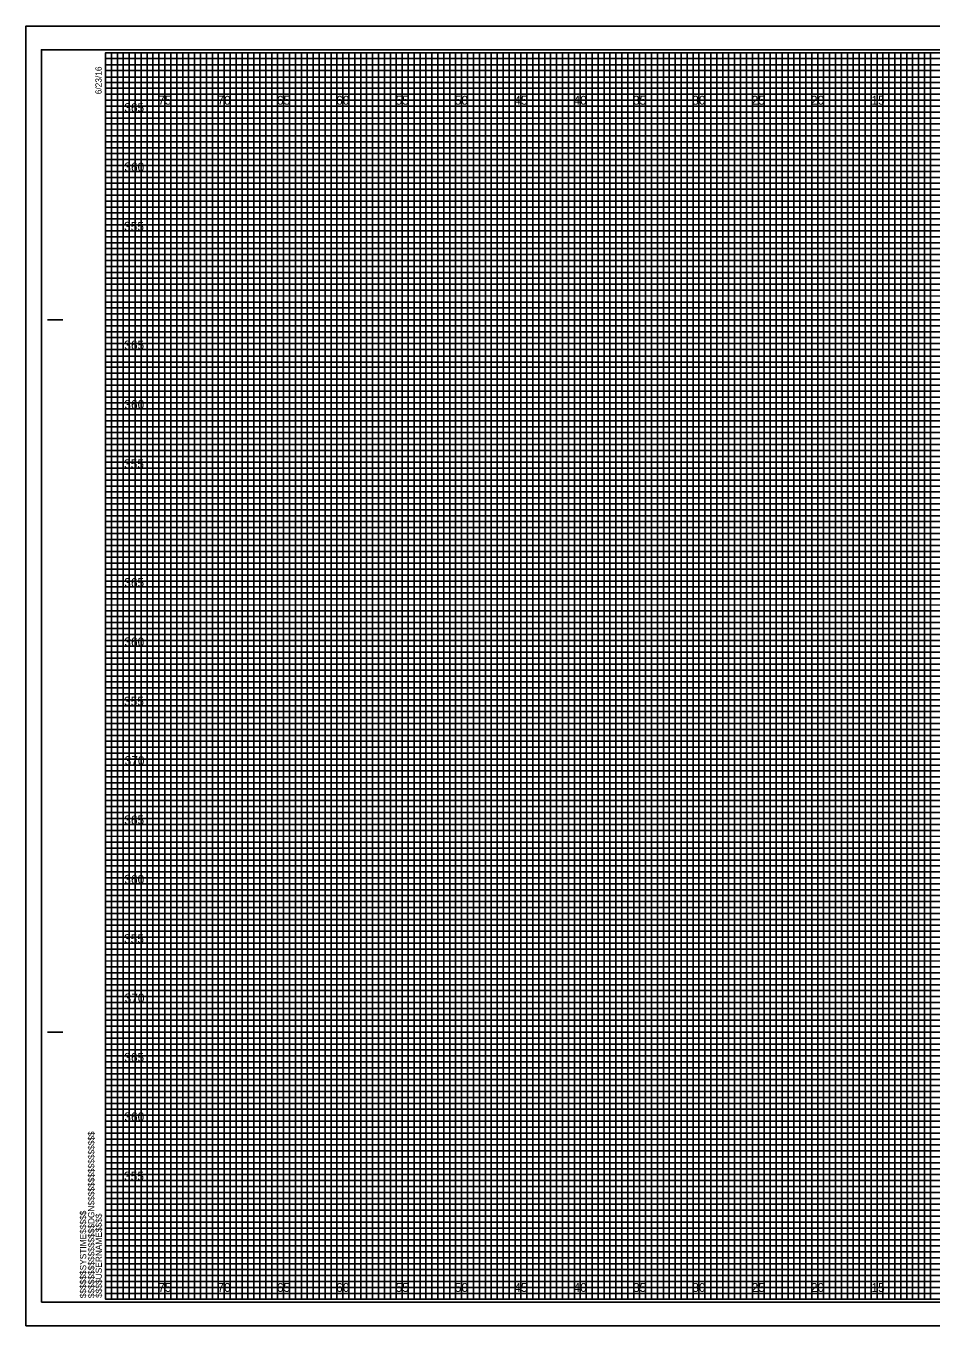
# Model space of a CAD drawing. Extents: x -7 to 162, y 658 to 767.
# Drawn here: x -6.7 to 69.5, y 657.8 to 767.2 of the extents above; entities that cross this region are included whole.
import ezdxf

# ---------------------------------------------------------------- set-up
doc = ezdxf.new("R2010")
doc.units = 0
for name, color, linetype in [('Prop XS Elevation Labels', 7, 'Continuous'), ('Prop XS Offset Labels', 7, 'Continuous'), ('Sheet Cross Section CELL', 7, 'Continuous'), ('Sheet Cross Section Grid Major CELL', 7, 'Continuous'), ('Sheet Cross Section Grid Middle CELL', 7, 'Continuous'), ('Sheet Cross Section Grid Minor 1 CELL', 7, 'Continuous'), ('Sheet Cross Section Grid Minor 2 CELL', 7, 'Continuous'), ('Sheet Cutting Line CELL', 7, 'Continuous'), ('Sheet DOT Grid CELL', 7, 'Continuous'), ('Sheet Plot Border Inside CELL', 7, 'Continuous'), ('Sheet Plot Border Outside CELL', 7, 'Continuous')]:
    doc.layers.add(name, color=color, linetype=linetype)

msp = doc.modelspace()

# ---------------------------------------------------------------- linework, layer by layer
at = {"layer": 'Sheet Cross Section CELL'}
for p, q in [((-4.9, 742.5), (-3.65, 742.5)), ((-4.85, 742.5), (-3.6, 742.5)), ((-4.9, 682.5), (-3.65, 682.5)), ((-4.85, 682.5), (-3.6, 682.5)), ((0, 660), (0, 660)), ((0, 660), (0, 660)), ((0, 660), (0, 660)), ((0, 660), (0, 660)), ((0, 660), (0, 660)), ((0, 660), (0, 660)), ((0, 660), (0, 660))]:
    msp.add_line(p, q, dxfattribs=at)
msp.add_lwpolyline([(160, 765), (0, 765), (0, 660), (160, 660)], close=True, dxfattribs=at)
at = {"layer": 'Sheet Cross Section Grid Major CELL'}
for p, q in [((5, 765), (0, 765)), ((5, 660), (5, 765)), ((15, 765), (10, 765)), ((10, 765), (10, 660)), ((15, 660), (15, 765)), ((25, 765), (20, 765)), ((20, 765), (20, 660)), ((25, 660), (25, 765)), ((35, 765), (30, 765)), ((30, 765), (30, 660)), ((35, 660), (35, 765)), ((45, 765), (40, 765)), ((40, 765), (40, 660)), ((45, 660), (45, 765)), ((55, 765), (50, 765)), ((50, 765), (50, 660)), ((55, 660), (55, 765)), ((65, 765), (60, 765)), ((60, 765), (60, 660)), ((65, 660), (65, 765)), ((10, 660), (5, 660)), ((20, 660), (15, 660)), ((30, 660), (25, 660)), ((40, 660), (35, 660)), ((50, 660), (45, 660)), ((60, 660), (55, 660)), ((70, 660), (65, 660))]:
    msp.add_line(p, q, dxfattribs=at)
for points in [[(0, 760), (160, 760), (160, 755), (0, 755)], [(0, 750), (160, 750), (160, 745), (0, 745)], [(0, 740), (160, 740), (160, 735), (0, 735)], [(0, 730), (160, 730), (160, 725), (0, 725)], [(0, 720), (160, 720), (160, 715), (0, 715)], [(0, 710), (160, 710), (160, 705), (0, 705)], [(0, 700), (160, 700), (160, 695), (0, 695)], [(0, 690), (160, 690), (160, 685), (0, 685)], [(0, 680), (160, 680), (160, 675), (0, 675)], [(0, 670), (160, 670), (160, 665), (0, 665)]]:
    msp.add_lwpolyline(points, dxfattribs=at)
at = {"layer": 'Sheet Cross Section Grid Middle CELL'}
for points in [[(0, 765), (2.5, 765), (2.5, 660), (7.5, 660), (7.5, 765), (12.5, 765), (12.5, 660), (17.5, 660), (17.5, 765), (22.5, 765), (22.5, 660), (27.5, 660), (27.5, 765), (32.5, 765), (32.5, 660), (37.5, 660), (37.5, 765), (42.5, 765), (42.5, 660), (47.5, 660), (47.5, 765), (52.5, 765), (52.5, 660), (57.5, 660), (57.5, 765), (62.5, 765), (62.5, 660), (67.5, 660), (67.5, 765), (72.5, 765)], [(0, 762.5), (137.5, 762.5)], [(0, 752.5), (160, 752.5), (160, 757.5), (0, 757.5)], [(0, 742.5), (160, 742.5), (160, 747.5), (0, 747.5)], [(0, 732.5), (160, 732.5), (160, 737.5), (0, 737.5)], [(0, 722.5), (160, 722.5), (160, 727.5), (0, 727.5)], [(0, 712.5), (160, 712.5), (160, 717.5), (0, 717.5)], [(0, 702.5), (160, 702.5), (160, 707.5), (0, 707.5)], [(0, 692.5), (160, 692.5), (160, 697.5), (0, 697.5)], [(0, 682.5), (160, 682.5), (160, 687.5), (0, 687.5)], [(0, 672.5), (160, 672.5), (160, 677.5), (0, 677.5)], [(0, 662.5), (160, 662.5), (160, 667.5), (0, 667.5)]]:
    msp.add_lwpolyline(points, dxfattribs=at)
at = {"layer": 'Sheet Cross Section Grid Minor 1 CELL'}
for p, q in [((0, 764.5), (130, 764.5)), ((130, 763.99), (0, 763.99)), ((0, 763.99), (0, 763.5)), ((0, 763.5), (130, 763.5)), ((130, 762.95), (0, 762.95)), ((0, 762.95), (0, 762)), ((0, 762), (160, 762))]:
    msp.add_line(p, q, dxfattribs=at)
for points in [[(0, 761.5), (135, 761.5), (160, 761.5), (160, 761), (0, 761)], [(0, 760.5), (160, 760.5), (160, 759.5), (0, 759.5)], [(0, 759), (160, 759), (160, 758.5), (0, 758.49)], [(0, 758), (160, 758), (160, 757), (0, 757)], [(0, 756.5), (160, 756.5), (160, 756), (0, 756)], [(0, 755.5), (160, 755.5), (160, 754.5), (0, 754.5)], [(0, 754), (160, 754), (160, 753.5), (0, 753.5)], [(0, 753), (160, 753), (160, 752), (0, 752)], [(0, 751.5), (160, 751.5), (160, 751), (0, 751)], [(0, 750.5), (160, 750.5), (160, 749.5), (0, 749.5)], [(0, 749), (160, 749), (160, 748.5), (0, 748.5)], [(0, 748), (160, 748), (160, 746.98), (160, 746.5), (160, 746), (0, 746)], [(0, 747), (160, 747), (160, 746.5), (0, 746.5)], [(0, 745.5), (160, 745.5), (160, 744.5), (0, 744.51)], [(0, 744.51), (160, 744.5), (160, 744), (0, 744)], [(0, 743.5), (160, 743.5), (160, 743), (0, 743)], [(0, 742), (160, 742), (160, 741.5), (0, 741.5)], [(0, 741), (160, 741), (160, 740.5), (0, 740.5)], [(-0.04, 739.45), (160, 739.45), (160, 738.94), (-0.04, 738.94)], [(0, 738.5), (160, 738.5), (160, 738), (0, 738)], [(0, 737), (160, 737), (160, 736.5), (0, 736.5)], [(0, 736), (160, 736), (160, 735.5), (0, 735.5)], [(0, 734.5), (160, 734.5), (160, 734), (0, 734)], [(0, 733.5), (160, 733.5), (160, 733), (0, 733)], [(0, 732), (160, 732), (160, 731.5), (0, 731.5)], [(0, 731), (160, 731), (160, 730.5), (0, 730.5)], [(0, 729.5), (160, 729.5), (160, 728.99), (0, 729)], [(0, 728.5), (160, 728.5), (160, 728), (0, 728)], [(0, 727), (160, 727), (160, 726.5), (0, 726.5)], [(0, 726), (160, 726), (160, 725.5), (0, 725.5)], [(0, 724.5), (160, 724.5), (160, 724), (0, 724)], [(0, 723.5), (160, 723.5), (160, 723), (0, 723)], [(0, 722), (160, 722), (160, 721.5), (0, 721.5)], [(0, 721), (160, 721), (160, 720.5), (0, 720.5)], [(0, 719.5), (160, 719.5), (160, 719), (0, 719)], [(0, 718.5), (160.03, 718.46), (160, 718), (0, 718)], [(0, 717), (160, 717), (160, 716.5), (0, 716.5)], [(0, 716), (160, 716), (160, 715.5), (0, 715.5)], [(0, 714.5), (160, 714.5), (160, 714), (0, 714)], [(0, 713.5), (160, 713.5), (160, 713), (0, 713)], [(0, 712), (160, 712), (160, 711.5), (0, 711.5)], [(0, 711), (160, 711), (160, 710.5), (0, 710.5)], [(0, 709.5), (160, 709.5), (160, 709), (0, 709)], [(0, 708.5), (160, 708.5), (160, 708), (0, 708)], [(0, 707), (160, 707), (160, 706.5), (0, 706.5)], [(0, 706), (160, 706), (160, 705.5), (0, 705.5)], [(0, 704.5), (160, 704.5), (160, 704), (0, 704)], [(0, 703.5), (160, 703.5), (160, 703), (0, 703)], [(0, 702), (160, 702), (160, 701.5), (0, 701.5)], [(0, 701), (160, 701), (160, 700.5), (0, 700.5)], [(0, 699.5), (160, 699.5), (160, 698.99), (0, 699)], [(0, 698.5), (160, 698.5), (160, 698), (0, 698)], [(0, 697), (160, 697), (160, 696.5), (0, 696.5)], [(0, 696), (160, 696), (160, 695.5), (0, 695.5)], [(0, 694.5), (160, 694.5), (160, 694), (0, 694)], [(0, 693.5), (160, 693.5), (160, 693), (0, 693)], [(0, 692), (160, 692), (160, 691.5), (0, 691.5)], [(0, 691), (160, 691), (160, 690.5), (0, 690.5)], [(0, 689.5), (160, 689.5), (160, 689), (0, 689)], [(0, 688.5), (160.03, 688.46), (160, 688), (0, 688)], [(0, 687), (160, 687), (160, 686.5), (0, 686.5)], [(0, 686), (160, 686), (160, 685.5), (0, 685.5)], [(0, 684.5), (160, 684.5), (160, 684), (0, 684)], [(0, 683.5), (160, 683.5), (160, 683), (0, 683)], [(0, 682), (160, 682), (160, 681.5), (0, 681.5)], [(0, 681), (160, 681), (160, 680.5), (0, 680.5)], [(0, 679.5), (160, 679.5), (160, 679), (0, 679)], [(0, 678.5), (160, 678.5), (160, 678), (0, 678)], [(0, 677), (160, 677), (160, 676.5), (0, 676.5)], [(0, 676), (160, 676), (160, 675.5), (0, 675.5)], [(0, 674.5), (160, 674.5), (160, 674), (0, 674)], [(0, 673.5), (160, 673.5), (160, 673), (0, 673)], [(0, 672), (160, 672), (160, 671.5), (0, 671.5)], [(0, 671), (160, 671), (160, 670.5), (0, 670.5)], [(0, 669.5), (160, 669.5), (160, 669), (0, 669)], [(0, 668.5), (160, 668.5), (160, 668), (0, 668)], [(0, 667), (160, 667), (160, 666.5), (0, 666.5)], [(0, 666), (160, 666), (160, 665.5), (0, 665.5)], [(0, 664.5), (160, 664.5), (160, 664), (0, 664)], [(0, 663.5), (160, 663.5), (160, 663), (0, 663)], [(0, 662), (160, 662), (160, 661.5), (0, 661.5)], [(0, 661), (160, 661), (160, 660.5), (0, 660.5)]]:
    msp.add_lwpolyline(points, dxfattribs=at)
at = {"layer": 'Sheet Cross Section Grid Minor 2 CELL'}
for points in [[(0, 660), (0.5, 660), (0.5, 765), (1, 765), (1, 660)], [(1, 660), (1.5, 660), (1.5, 765), (2, 765), (2, 660)], [(2.5, 660), (3, 660), (3, 765), (3.5, 765), (3.5, 660)], [(3.5, 660), (4, 660), (4, 765), (4.5, 765), (4.5, 660)], [(5, 660), (5.5, 660), (5.5, 765), (6, 765), (6, 660)], [(6, 660), (6.5, 660), (6.5, 765), (7, 765), (7, 660)], [(7.5, 660), (8, 660), (8, 765), (8.5, 765), (8.5, 660)], [(8.5, 660), (9, 660), (9, 765), (9.5, 765), (9.5, 660)], [(10, 660), (10.5, 660), (10.5, 765), (11, 765), (11, 660)], [(11, 660), (11.5, 660), (11.5, 765), (12, 765), (12, 660)], [(12.5, 660), (13, 660), (13, 765), (13.5, 765), (13.5, 660)], [(13.5, 660), (14, 660), (14, 765), (14.5, 765), (14.5, 660)], [(15, 660), (15.5, 660), (15.5, 765), (16, 765), (16, 660)], [(16, 660), (16.5, 660), (16.5, 765), (17, 765), (17, 660)], [(17.5, 660), (18, 660), (18, 765), (18.5, 765), (18.5, 660)], [(18.5, 660), (19, 660), (19, 765), (19.5, 765), (19.5, 660)], [(20, 660), (20.5, 660), (20.5, 765), (21, 765), (21, 660)], [(21, 660), (21.5, 660), (21.5, 765), (22, 765), (22, 660)], [(22.5, 660), (23, 660), (23, 765), (23.5, 765), (23.5, 660)], [(23.5, 660), (24, 660), (24, 765), (24.5, 765), (24.5, 660)], [(25, 660), (25.5, 660), (25.5, 765), (26, 765), (26, 660)], [(26, 660), (26.5, 660), (26.5, 765), (27, 765), (27, 660)], [(27.5, 660), (28, 660), (28, 765), (28.5, 765), (28.5, 660)], [(28.5, 660), (29, 660), (29, 765), (29.5, 765), (29.5, 660)], [(30, 660), (30.5, 660), (30.5, 765), (31, 765), (31, 660)], [(31, 660), (31.5, 660), (31.5, 765), (32, 765), (32, 660)], [(32.5, 660), (33, 660), (33, 765), (33.5, 765), (33.5, 660)], [(33.5, 660), (34, 660), (34, 765), (34.5, 765), (34.5, 660)], [(35, 660), (35.5, 660), (35.5, 765), (36, 765), (36, 660)], [(36, 660), (36.5, 660), (36.5, 765), (37, 765), (37, 660)], [(37.5, 660), (38, 660), (38, 765), (38.5, 765), (38.5, 660)], [(38.5, 660), (39, 660), (39, 765), (39.5, 765), (39.5, 660)], [(40, 660), (40.5, 660), (40.5, 765), (41, 765), (41, 660)], [(41, 660), (41.5, 660), (41.5, 765), (42, 765), (42, 660)], [(42.5, 660), (43, 660), (43, 765), (43.5, 765), (43.5, 660)], [(43.5, 660), (44, 660), (44, 765), (44.5, 765), (44.5, 660)], [(45, 660), (45.5, 660), (45.5, 765), (46, 765), (46, 660)], [(46, 660), (46.5, 660), (46.5, 765), (47, 765), (47, 660)], [(47.5, 660), (48, 660), (48, 765), (48.5, 765), (48.5, 660)], [(48.5, 660), (49, 660), (49, 765), (49.5, 765), (49.5, 660)], [(50, 660), (50.5, 660), (50.5, 765), (51, 765), (51, 660)], [(51, 660), (51.5, 660), (51.5, 765), (52, 765), (52, 660)], [(52.5, 660), (53, 660), (53, 765), (53.5, 765), (53.5, 660)], [(53.5, 660), (54, 660), (54, 765), (54.5, 765), (54.5, 660)], [(55, 660), (55.5, 660), (55.5, 765), (56, 765), (56, 660)], [(56, 660), (56.5, 660), (56.5, 765), (57, 765), (57, 660)], [(57.5, 660), (58, 660), (58, 765), (58.5, 765), (58.5, 660)], [(58.5, 660), (59, 660), (59, 765), (59.5, 765), (59.5, 660)], [(60, 660), (60.5, 660), (60.5, 765), (61, 765), (61, 660)], [(61, 660), (61.5, 660), (61.5, 765), (62, 765), (62, 660)], [(62.5, 660), (63, 660), (63, 765), (63.5, 765), (63.5, 660)], [(63.5, 660), (64, 660), (64, 765), (64.5, 765), (64.5, 660)], [(65, 660), (65.5, 660), (65.5, 765), (66, 765), (66, 660)], [(66, 660), (66.5, 660), (66.5, 765), (67, 765), (67, 660)], [(67.5, 660), (68, 660), (68, 765), (68.5, 765), (68.5, 660)], [(68.5, 660), (69, 660), (69, 765), (69.5, 765), (69.5, 660)]]:
    msp.add_lwpolyline(points, dxfattribs=at)
at = {"layer": 'Sheet Cutting Line CELL'}
for p, q in [((161.65, 767.25), (-6.7, 767.25)), ((-6.7, 767.25), (-6.7, 657.75)), ((-6.7, 657.75), (161.65, 657.75))]:
    msp.add_line(p, q, dxfattribs=at)
at = {"layer": 'Sheet DOT Grid CELL'}
for p, q in [((5, 660), (5, 765)), ((10, 660), (10, 765)), ((15, 660), (15, 765)), ((20, 660), (20, 765)), ((25, 660), (25, 765)), ((30, 660), (30, 765)), ((35, 660), (35, 765)), ((40, 660), (40, 765)), ((45, 660), (45, 765)), ((50, 660), (50, 765)), ((55, 660), (55, 765)), ((60, 660), (60, 765)), ((65, 660), (65, 765)), ((0, 760), (160, 760)), ((0, 755), (160, 755)), ((0, 750), (160, 750)), ((0, 745), (160, 745)), ((0, 740), (160, 740)), ((0, 735), (160, 735)), ((0, 730), (160, 730)), ((0, 725), (160, 725)), ((0, 720), (160, 720)), ((0, 715), (160, 715)), ((0, 710), (160, 710)), ((0, 705), (160, 705)), ((0, 700), (160, 700)), ((0, 695), (160, 695)), ((0, 690), (160, 690)), ((0, 685), (160, 685)), ((0, 680), (160, 680)), ((0, 675), (160, 675)), ((0, 670), (160, 670)), ((0, 665), (160, 665))]:
    msp.add_line(p, q, dxfattribs=at)
at = {"layer": 'Sheet Plot Border Inside CELL'}
msp.add_lwpolyline([(-5.4, 659.75), (161.2, 659.75), (161.2, 765.25), (-5.4, 765.25)], close=True, dxfattribs=at)
at = {"layer": 'Sheet Plot Border Outside CELL'}
msp.add_lwpolyline([(-6.7, 657.75), (161.65, 657.75), (161.65, 767.25), (-6.7, 767.25)], close=True, dxfattribs=at)

# ---------------------------------------------------------------- texts
at = {"layer": 'Prop XS Elevation Labels'}
for s, p in [('365', (1.58, 760)), ('360', (1.59, 755)), ('355', (1.56, 750)), ('365', (1.58, 740)), ('360', (1.59, 735)), ('355', (1.56, 730)), ('365', (1.58, 720)), ('360', (1.59, 715)), ('355', (1.56, 710)), ('370', (1.61, 705)), ('365', (1.58, 700)), ('360', (1.59, 695)), ('355', (1.56, 690)), ('370', (1.61, 685)), ('365', (1.58, 680)), ('360', (1.59, 675)), ('355', (1.56, 670))]:
    msp.add_text(s, height=0.75, dxfattribs=at).set_placement(p)
at = {"layer": 'Prop XS Offset Labels'}
for s, p in [('75', (4.44, 760.62)), ('70', (9.43, 760.62)), ('65', (14.44, 760.62)), ('60', (19.43, 760.62)), ('55', (24.44, 760.62)), ('50', (29.43, 760.62)), ('45', (34.44, 760.62)), ('40', (39.43, 760.62)), ('35', (44.44, 760.62)), ('30', (49.43, 760.62)), ('25', (54.44, 760.62)), ('20', (59.43, 760.62)), ('15', (64.53, 760.62)), ('70', (9.43, 660.62)), ('65', (14.44, 660.62)), ('60', (19.43, 660.62)), ('50', (29.43, 660.62)), ('40', (39.43, 660.62)), ('35', (44.44, 660.62)), ('30', (49.43, 660.62)), ('25', (54.44, 660.62)), ('20', (59.43, 660.62)), ('75', (4.44, 660.62)), ('55', (24.44, 660.62)), ('45', (34.44, 660.62)), ('15', (64.53, 660.62))]:
    msp.add_text(s, height=0.75, dxfattribs=at).set_placement(p)
at = {"layer": 'Sheet Cross Section CELL'}
for s, p in [('6/23/16', (-0.33, 761.5)), ('$$$$$$$$$$$$$$$$DGN$$$$$$$$$$$$$$$$', (-0.94, 660.09)), ('$$$$$$SYSTIME$$$$$', (-1.63, 660.09)), ('$$$$USERNAME$$$$', (-0.31, 660.12))]:
    msp.add_text(s, height=0.525, rotation=90, dxfattribs=at).set_placement(p)

doc.saveas('drawing.dxf')
